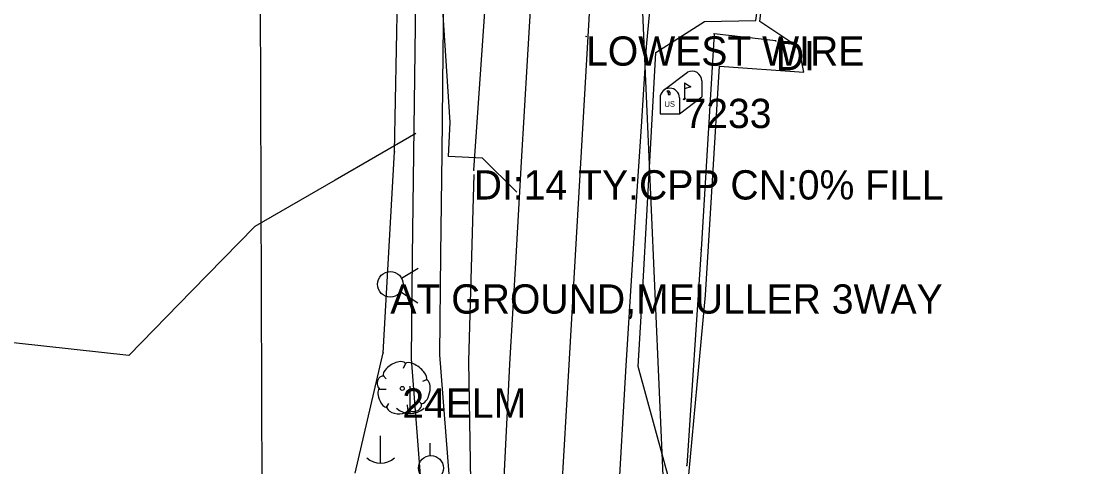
# Model space of a CAD drawing. Extents: x 997398 to 1003416, y 334596 to 337085.
# Drawn here: x 999156 to 999337.6, y 335405.4 to 335481.5 of the extents above; entities that cross this region are included whole.
import ezdxf

# ---------------------------------------------------------------- set-up
doc = ezdxf.new("R2010")
doc.units = 0
for name, color, linetype in [('Default', 7, 'Continuous'), ('S_DITCHLINE', 7, 'Continuous'), ('S_DRG_PT_SYM', 7, 'Continuous'), ('S_DRIVEWAY', 7, 'Continuous'), ('S_EDGE_PAVEMENT', 7, 'Continuous'), ('S_ELECTRIC_UTILITIES_ANNOT', 7, 'Continuous'), ('S_FENCE', 7, 'Continuous'), ('S_FENCE_ANNOT', 7, 'Continuous'), ('S_GAS_UTILITIES', 7, 'Continuous'), ('S_GRAVEL_ROAD', 7, 'Continuous'), ('S_GRD_PT_SYM', 7, 'Continuous'), ('S_MAILBOX', 7, 'Continuous'), ('S_MAILBOX_ANNOT', 7, 'Continuous'), ('S_MSC_PT_SYM', 7, 'Continuous'), ('S_PAVEMENT_CROWN', 7, 'Continuous'), ('S_SANITARY_SEWER', 7, 'Continuous'), ('S_SIDE_DRAIN', 7, 'Continuous'), ('S_SIDE_DRAIN_ANNOT', 7, 'Continuous'), ('S_SIDEWALK', 7, 'Continuous'), ('S_TREE', 7, 'Continuous'), ('S_TREE_ANNOT', 7, 'Continuous'), ('S_UTILITY_POLE', 7, 'Continuous'), ('S_UTL_PT_SYM', 7, 'Continuous'), ('S_WATER_UTILITIES', 7, 'Continuous'), ('S_WATER_UTILITIES_ANNOT', 7, 'Continuous')]:
    doc.layers.add(name, color=color, linetype=linetype)

msp = doc.modelspace()

# ---------------------------------------------------------------- linework, layer by layer
at = {"layer": 'Default'}
msp.add_line((999272.07, 335256.17), (999254.77, 335651.12), dxfattribs=at)
at = {"layer": 'S_DITCHLINE'}
msp.add_lwpolyline([(999233.13, 335382.37), (999232.78, 335402.91), (999232.42, 335423.45), (999232.88, 335439.39), (999233.34, 335455.34)], dxfattribs=at)
at = {"layer": 'S_DRG_PT_SYM'}
msp.add_lwpolyline([(999233.26, 335456.06), (999233.26, 335456.11), (999233.26, 335456.06), (999233.21, 335456.06), (999233.26, 335456.06), (999233.26, 335456.01), (999233.26, 335456.06), (999233.31, 335456.06)], dxfattribs=at)
at = {"layer": 'S_DRIVEWAY'}
msp.add_lwpolyline([(999240.62, 335452.32), (999234.74, 335458.11), (999228.93, 335458.39), (999229.26, 335464.28), (999227.96, 335483.47), (999242.96, 335490.88)], dxfattribs=at)
at = {"layer": 'S_EDGE_PAVEMENT'}
for points in [[(999250.53, 335290.61), (999251.9, 335310.31), (999253.28, 335330), (999254.66, 335349.69), (999256.03, 335369.39), (999256.96, 335383.69), (999257.89, 335397.99), (999259.31, 335422.72), (999260.17, 335436.32), (999261.04, 335449.92), (999261.9, 335463.52), (999262.77, 335477.12), (999265.06, 335501.55), (999266.67, 335519.12), (999268.27, 335536.68), (999270.61, 335550.38), (999272.95, 335564.07), (999275.29, 335577.76), (999277.63, 335591.45)], [(999268.87, 335320.6), (999263.53, 335329.26), (999260.4, 335340), (999260.03, 335350.15), (999261.25, 335369.32), (999262.19, 335383.58), (999263.12, 335397.84), (999266.91, 335402.13), (999261.38, 335422.51), (999262.14, 335435.92), (999262.89, 335449.33), (999263.64, 335462.75), (999264.4, 335476.16), (999272.66, 335481.44), (999281.46, 335481.65), (999283.33, 335495.44), (999285.2, 335509.23), (999269.56, 335528.03), (999269.81, 335536.47), (999271.83, 335550.21), (999273.84, 335563.95), (999275.86, 335577.69), (999277.88, 335591.43)], [(999345.08, 335310.18), (999333.98, 335310.31), (999320.35, 335310.66), (999320.34, 335309.11), (999300.42, 335309.96), (999290.95, 335313.05), (999280.99, 335317.76), (999276.64, 335321.37), (999273.81, 335324.29), (999269.4, 335331.28), (999266.59, 335340.08), (999266.2, 335350.38), (999267.62, 335372.46), (999269.1, 335395.3), (999271.9, 335398.47), (999270.02, 335404.05), (999271.44, 335419.38), (999272.86, 335434.71), (999274.05, 335454.26), (999275.25, 335473.81), (999289.66, 335472.83), (999288.8, 335477.03), (999282.16, 335481.48), (999283.77, 335495.62)], [(999231.23, 335279.53), (999232.05, 335292.74), (999233.23, 335312.98), (999234.4, 335333.23), (999235.91, 335357.55), (999237.41, 335381.87), (999238.41, 335402.4), (999239.41, 335422.94), (999240.43, 335440.22), (999241.44, 335457.5), (999242.46, 335474.78), (999243.48, 335492.06)]]:
    msp.add_lwpolyline(points, dxfattribs=at)
at = {"layer": 'S_FENCE'}
for p, q in [((999274.33, 335479.38), (999272.09, 335442.51)), ((999284.88, 335478.14), (999274.33, 335479.38)), ((999272.09, 335442.51), (999269.66, 335405.61))]:
    msp.add_line(p, q, dxfattribs=at)
at = {"layer": 'S_GAS_UTILITIES'}
for p, q in [((999219.71, 335459.22), (999220.7, 335507.17)), ((999217.81, 335424.88), (999219.71, 335459.22)), ((999213.02, 335404.29), (999217.81, 335424.88))]:
    msp.add_line(p, q, dxfattribs=at)
at = {"layer": 'S_GRAVEL_ROAD'}
msp.add_lwpolyline([(999223.35, 335462.34), (999209.62, 335454.39), (999195.89, 335446.44), (999185.13, 335435.44), (999174.37, 335424.44), (999155.18, 335426.53), (999135.99, 335428.62), (999118.12, 335430.08), (999100.25, 335431.54), (999098.47, 335450.56), (999096.69, 335469.59), (999076.88, 335473.01), (999057.06, 335476.44)], dxfattribs=at)
at = {"layer": 'S_GRD_PT_SYM'}
msp.add_lwpolyline([(999252.45, 335478.92), (999252.45, 335478.97), (999252.45, 335478.92), (999252.4, 335478.92), (999252.45, 335478.92), (999252.45, 335478.87), (999252.45, 335478.92), (999252.5, 335478.92)], dxfattribs=at)
at = {"layer": 'S_MAILBOX'}
for p, q in [((999265.64, 335469.68), (999269.78, 335472.79)), ((999272.21, 335471.32), (999272.21, 335468.6)), ((999269.26, 335470.97), (999269.26, 335468.26)), ((999265.09, 335468.41), (999265.09, 335465.7)), ((999268.41, 335465.7), (999272.21, 335468.6)), ((999268.41, 335468.41), (999268.41, 335465.7)), ((999265.09, 335465.7), (999268.41, 335465.7))]:
    msp.add_line(p, q, dxfattribs=at)
for points in [[(999266.27, 335469.53), (999266.49, 335469.39), (999266.49, 335469), (999266.8, 335469), (999266.8, 335469.36), (999266.61, 335469.61), (999266.27, 335469.55)], [(999269.26, 335470.97), (999270.37, 335470.31), (999269.26, 335469.96)]]:
    msp.add_lwpolyline(points, dxfattribs=at)
for centre, end in [((999270.55, 335471.32), 117.5718), ((999266.75, 335468.41), 180)]:
    msp.add_arc(centre, 1.66, 0, end, dxfattribs=at)
msp.add_ellipse((999269.26, 335468.26), major_axis=(0.145, 0.132), ratio=0.564646, dxfattribs=at)
at = {"layer": 'S_MSC_PT_SYM'}
for points in [[(999274.33, 335479.38), (999274.33, 335479.43), (999274.33, 335479.38), (999274.28, 335479.38), (999274.33, 335479.38), (999274.33, 335479.33), (999274.33, 335479.38), (999274.38, 335479.38)], [(999284.88, 335478.14), (999284.88, 335478.19), (999284.88, 335478.14), (999284.83, 335478.14), (999284.88, 335478.14), (999284.88, 335478.09), (999284.88, 335478.14), (999284.93, 335478.14)], [(999272.09, 335442.51), (999272.09, 335442.56), (999272.09, 335442.51), (999272.04, 335442.51), (999272.09, 335442.51), (999272.09, 335442.46), (999272.09, 335442.51), (999272.14, 335442.51)], [(999269.66, 335405.61), (999269.66, 335405.66), (999269.66, 335405.61), (999269.61, 335405.61), (999269.66, 335405.61), (999269.66, 335405.56), (999269.66, 335405.61), (999269.71, 335405.61)]]:
    msp.add_lwpolyline(points, dxfattribs=at)
at = {"layer": 'S_PAVEMENT_CROWN'}
msp.add_lwpolyline([(999240.93, 335269.15), (999242.42, 335292.45), (999243.36, 335312.31), (999244.3, 335332.17), (999245.73, 335356.52), (999247.17, 335380.88), (999248.33, 335401.35), (999249.49, 335421.83), (999250.52, 335439.55), (999251.54, 335457.27), (999252.57, 335474.99), (999253.6, 335492.71), (999255.46, 335505.53), (999257.33, 335518.35), (999259.19, 335531.16), (999261.06, 335543.98), (999262.92, 335556.8), (999264.79, 335569.61), (999266.65, 335582.43), (999268.52, 335595.25), (999272.87, 335613.5), (999277.22, 335631.74), (999281.77, 335646.2)], dxfattribs=at)
at = {"layer": 'S_SANITARY_SEWER'}
msp.add_line((999197.31, 335352.9), (999196.62, 335551), dxfattribs=at)
at = {"layer": 'S_SIDE_DRAIN'}
msp.add_line((999233.26, 335456.06), (999241.18, 335570.41), dxfattribs=at)
at = {"layer": 'S_SIDEWALK'}
for points in [[(999214.01, 335280.58), (999214.8, 335292.62), (999216.16, 335313.46), (999217.52, 335334.3), (999218.07, 335347.06), (999218.63, 335359.82), (999222.21, 335371.88), (999225.78, 335383.94), (999224.2, 335403.9), (999222.62, 335423.86), (999222.83, 335441.35), (999223.04, 335458.84), (999223.26, 335476.33), (999223.47, 335493.82), (999224.42, 335507.61), (999225.37, 335521.4), (999226.32, 335535.18), (999227.27, 335548.97)], [(999225.73, 335271.38), (999218.89, 335281.67), (999219.66, 335292.48), (999220.98, 335313.22), (999222.31, 335333.97), (999223.3, 335346.79), (999224.29, 335359.6), (999230.64, 335383.76), (999229.05, 335404.13), (999227.47, 335424.5), (999227.67, 335441.74), (999227.86, 335458.99), (999228.06, 335476.23), (999228.26, 335493.48), (999229.22, 335507.16), (999230.18, 335520.85), (999231.14, 335534.54), (999232.1, 335548.22)]]:
    msp.add_lwpolyline(points, dxfattribs=at)
at = {"layer": 'S_TREE'}
for p, q in [((999221.62, 335423.02), (999221.23, 335422.17)), ((999217.82, 335421.01), (999218.33, 335420.43)), ((999217.16, 335418.68), (999218.29, 335418.68)), ((999225.19, 335420.23), (999224.53, 335419.96)), ((999218.33, 335415.5), (999218.79, 335416.2)), ((999222.01, 335415.23), (999221.93, 335416.01)), ((999224.41, 335416.12), (999223.95, 335416.55))]:
    msp.add_line(p, q, dxfattribs=at)
msp.add_circle((999221.06, 335418.78), 0.341, dxfattribs=at)
for centre, major_axis, ratio, start_param, end_param in [((999219.73, 335421.98), (1.86, 1.08), 0.471018, 0, 3.141593), ((999223.38, 335421.66), (-1.81, 1.36), 0.405113, 3.141593, 6.283186), ((999217.49, 335419.86), (0.31, 1.03), 0.646762, 0, 3.141593), ((999217.8, 335417.21), (-0.61, 1.6), 0.420543, 6.283185, 9.424777), ((999224.74, 335418.25), (0.46, 2.04), 0.482994, 3.141593, 6.283185), ((999220.26, 335415.43), (-1.83, 0.19), 0.529943, 0, 3.141593), ((999223.22, 335415.73), (1.09, 0.46), 0.711534, 3.141592, 6.283185)]:
    msp.add_ellipse(centre, major_axis=major_axis, ratio=ratio, start_param=start_param, end_param=end_param, dxfattribs=at)
at = {"layer": 'S_UTILITY_POLE'}
for p, q in [((999222.37, 335419.19), (999222.37, 335414.47)), ((999217.3, 335410.71), (999217.3, 335405.98)), ((999225.82, 335407.34), (999225.82, 335409.44))]:
    msp.add_line(p, q, dxfattribs=at)
msp.add_circle((999225.95, 335405.19), 2.13, dxfattribs=at)
for centre in [(999222.43, 335417.89), (999217.37, 335409.41)]:
    msp.add_arc(centre, 3.41, 226.3972, 313.6028, dxfattribs=at)
at = {"layer": 'S_UTL_PT_SYM'}
for points in [[(999252.45, 335478.92), (999252.45, 335478.97), (999252.45, 335478.92), (999252.4, 335478.92), (999252.45, 335478.92), (999252.45, 335478.87), (999252.45, 335478.92), (999252.5, 335478.92)], [(999219.71, 335459.22), (999219.71, 335459.27), (999219.71, 335459.22), (999219.66, 335459.22), (999219.71, 335459.22), (999219.71, 335459.17), (999219.71, 335459.22), (999219.76, 335459.22)], [(999217.81, 335424.88), (999217.81, 335424.93), (999217.81, 335424.88), (999217.76, 335424.88), (999217.81, 335424.88), (999217.81, 335424.83), (999217.81, 335424.88), (999217.86, 335424.88)]]:
    msp.add_lwpolyline(points, dxfattribs=at)
at = {"layer": 'S_WATER_UTILITIES'}
for p, q in [((999220.92, 335437.62), (999223.75, 335439.35)), ((999220.8, 335435.31), (999223.71, 335433.39))]:
    msp.add_line(p, q, dxfattribs=at)
msp.add_circle((999219.02, 335436.57), 2.18, dxfattribs=at)

# ---------------------------------------------------------------- texts
at = {"layer": 'S_ELECTRIC_UTILITIES_ANNOT'}
msp.add_text('LOWEST WIRE', height=5, dxfattribs=at).set_placement((999252.45, 335473.92))
at = {"layer": 'S_FENCE_ANNOT'}
msp.add_text('DI', height=5, dxfattribs=at).set_placement((999284.88, 335473.14))
at = {"layer": 'S_MAILBOX'}
msp.add_text('US', height=0.96, rotation=360, dxfattribs=at).set_placement((999265.85, 335466.89))
at = {"layer": 'S_MAILBOX_ANNOT'}
msp.add_text('7233', height=5, dxfattribs=at).set_placement((999269.26, 335463.26))
at = {"layer": 'S_SIDE_DRAIN_ANNOT'}
msp.add_text('DI:14 TY:CPP CN:0% FILL', height=5, dxfattribs=at).set_placement((999233.26, 335451.06))
at = {"layer": 'S_TREE_ANNOT'}
msp.add_text('24ELM', height=5, dxfattribs=at).set_placement((999221.06, 335413.78))
at = {"layer": 'S_WATER_UTILITIES_ANNOT'}
msp.add_text('AT GROUND,MEULLER 3WAY', height=5, dxfattribs=at).set_placement((999219.02, 335431.57))

doc.saveas('drawing.dxf')
